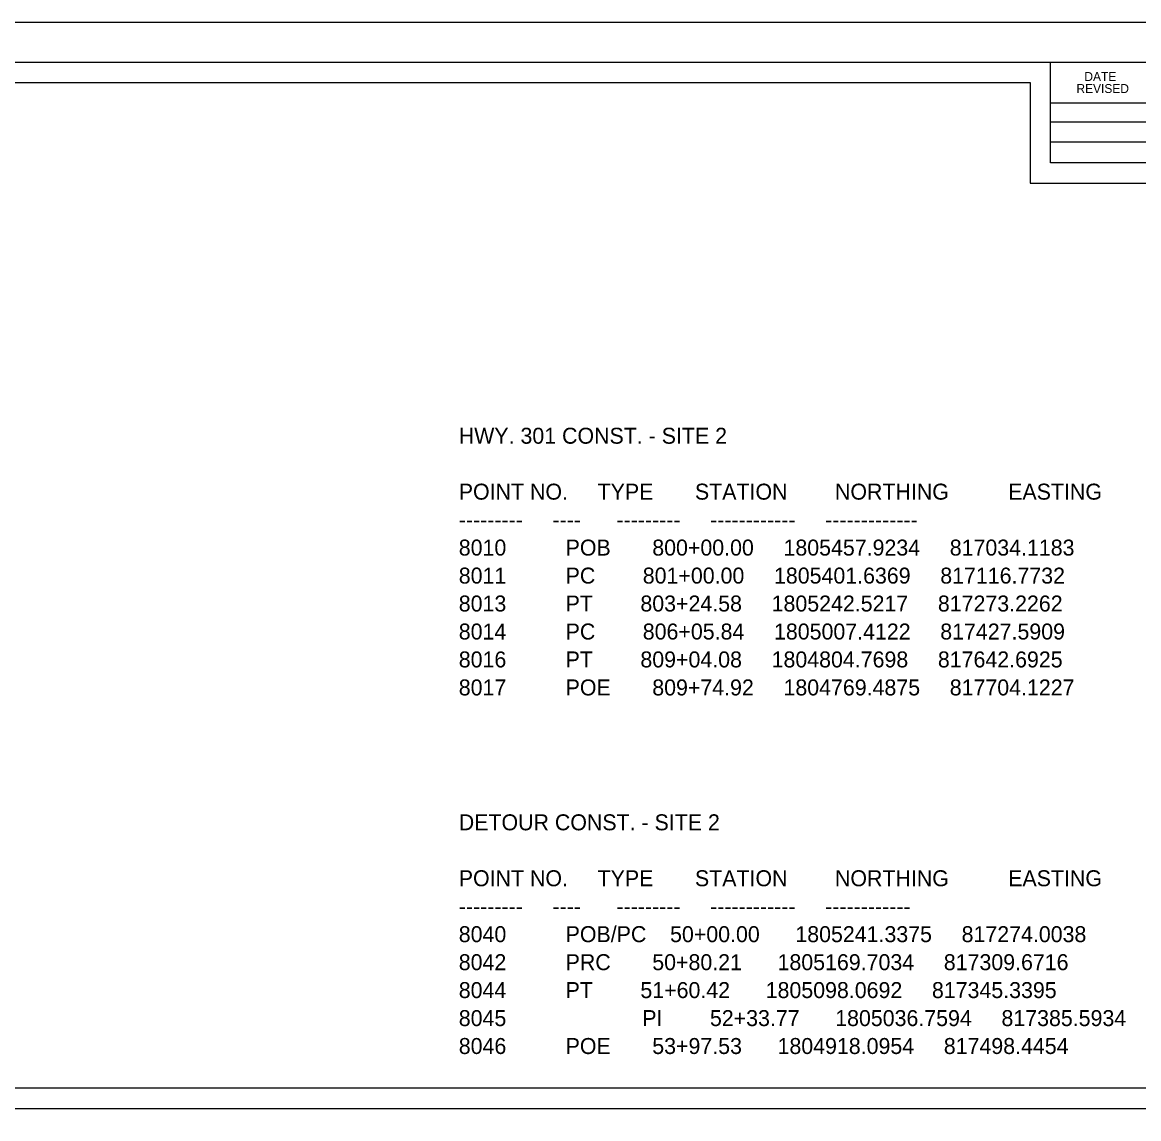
# Model space of a CAD drawing. Extents: x 818639 to 819473, y 1805980 to 1806194.
# Drawn here: x 819304.2 to 819413.8, y 1806086 to 1806193.7 of the extents above; entities that cross this region are included whole.
import ezdxf

# ---------------------------------------------------------------- set-up
doc = ezdxf.new("R2010")
doc.units = 0
for name, color, linetype in [('R_Border', 7, 'Continuous'), ('R_Border Plan-Plan', 7, 'Continuous'), ('R_Draft', 7, 'Continuous'), ('R_No Plot', 7, 'Continuous')]:
    doc.layers.add(name, color=color, linetype=linetype)

msp = doc.modelspace()

# ---------------------------------------------------------------- linework, layer by layer
at = {"layer": 'R_Border'}
for p, q in [((819151.6, 1806189.77), (819467.78, 1806189.77)), ((819405.14, 1806179.89), (819405.14, 1806189.77)), ((819405.14, 1806185.75), (819424.68, 1806185.75)), ((819405.14, 1806183.89), (819424.68, 1806183.89)), ((819405.14, 1806181.95), (819424.68, 1806181.95)), ((819467.78, 1806179.89), (819405.14, 1806179.89))]:
    msp.add_line(p, q, dxfattribs=at)
at = {"layer": 'R_Border Plan-Plan'}
msp.add_line((819151.6, 1806087.04), (819467.78, 1806087.04), dxfattribs=at)
at = {"layer": 'R_No Plot'}
for points in [[(819139.19, 1806193.67), (819472.53, 1806193.67), (819472.53, 1805980.33), (819139.19, 1805980.33)], [(819465.78, 1806089.04), (819153.6, 1806089.04), (819153.6, 1806187.77), (819403.14, 1806187.77), (819403.14, 1806177.89), (819420.68, 1806177.89), (819444.78, 1806177.89), (819444.78, 1806155.56), (819465.78, 1806155.56)], [(819153.6, 1806187.77), (819403.14, 1806187.77), (819403.14, 1806177.89), (819420.68, 1806177.89), (819444.78, 1806177.89), (819444.78, 1806155.56), (819465.78, 1806155.56), (819465.78, 1805986.31), (819153.6, 1805986.31)]]:
    msp.add_lwpolyline(points, close=True, dxfattribs=at)

# ---------------------------------------------------------------- texts
at = {"layer": 'R_Border'}
for s, p in [('DATE', (819408.48, 1806187.91)), ('REVISED', (819407.7, 1806186.73))]:
    msp.add_text(s, height=0.879, dxfattribs=at).set_placement(p)
at = {"layer": 'R_Draft'}
for s, height, p in [('HWY. 301 CONST. - SITE 2', 1.5686, (819347.04, 1806152.3)), ('POINT NO.     TYPE       STATION        NORTHING          EASTING ', 1.5686, (819347.04, 1806146.81)), ('---------     ----      ---------     ------------     -------------', 1.5686, (819347.04, 1806144.06)), ('8010          POB       800+00.00     1805457.9234     817034.1183', 1.5686, (819347.04, 1806141.32)), ('8011          PC        801+00.00     1805401.6369     817116.7732', 1.5686, (819347.04, 1806138.57)), ('8013          PT        803+24.58     1805242.5217     817273.2262', 1.5686, (819347.04, 1806135.83)), ('8014          PC        806+05.84     1805007.4122     817427.5909', 1.5686, (819347.04, 1806133.08)), ('8016          PT        809+04.08     1804804.7698     817642.6925', 1.5686, (819347.04, 1806130.34)), ('8017          POE       809+74.92     1804769.4875     817704.1227', 1.5686, (819347.04, 1806127.59)), ('DETOUR CONST. - SITE 2', 1.5686, (819347.04, 1806114.35)), ('POINT NO.     TYPE       STATION        NORTHING          EASTING ', 1.5686, (819347.04, 1806108.86)), ('---------     ----      ---------     ------------     ------------ ', 1.5686, (819347.04, 1806106.11)), ('8040          POB/PC    50+00.00      1805241.3375     817274.0038', 1.5686, (819347.04, 1806103.37)), ('8042          PRC       50+80.21      1805169.7034     817309.6716', 1.5686, (819347.04, 1806100.62)), ('8044          PT        51+60.42      1805098.0692     817345.3395', 1.5686, (819347.04, 1806097.88)), ('8045', 1.569, (819347.04, 1806095.13)), ('    PI        52+33.77      1805036.7594     817385.5934', 1.5686, (819362.73, 1806095.13)), ('8046          POE       53+97.53      1804918.0954     817498.4454', 1.5686, (819347.04, 1806092.39))]:
    msp.add_text(s, height=height, dxfattribs=at).set_placement(p)

doc.saveas('drawing.dxf')
